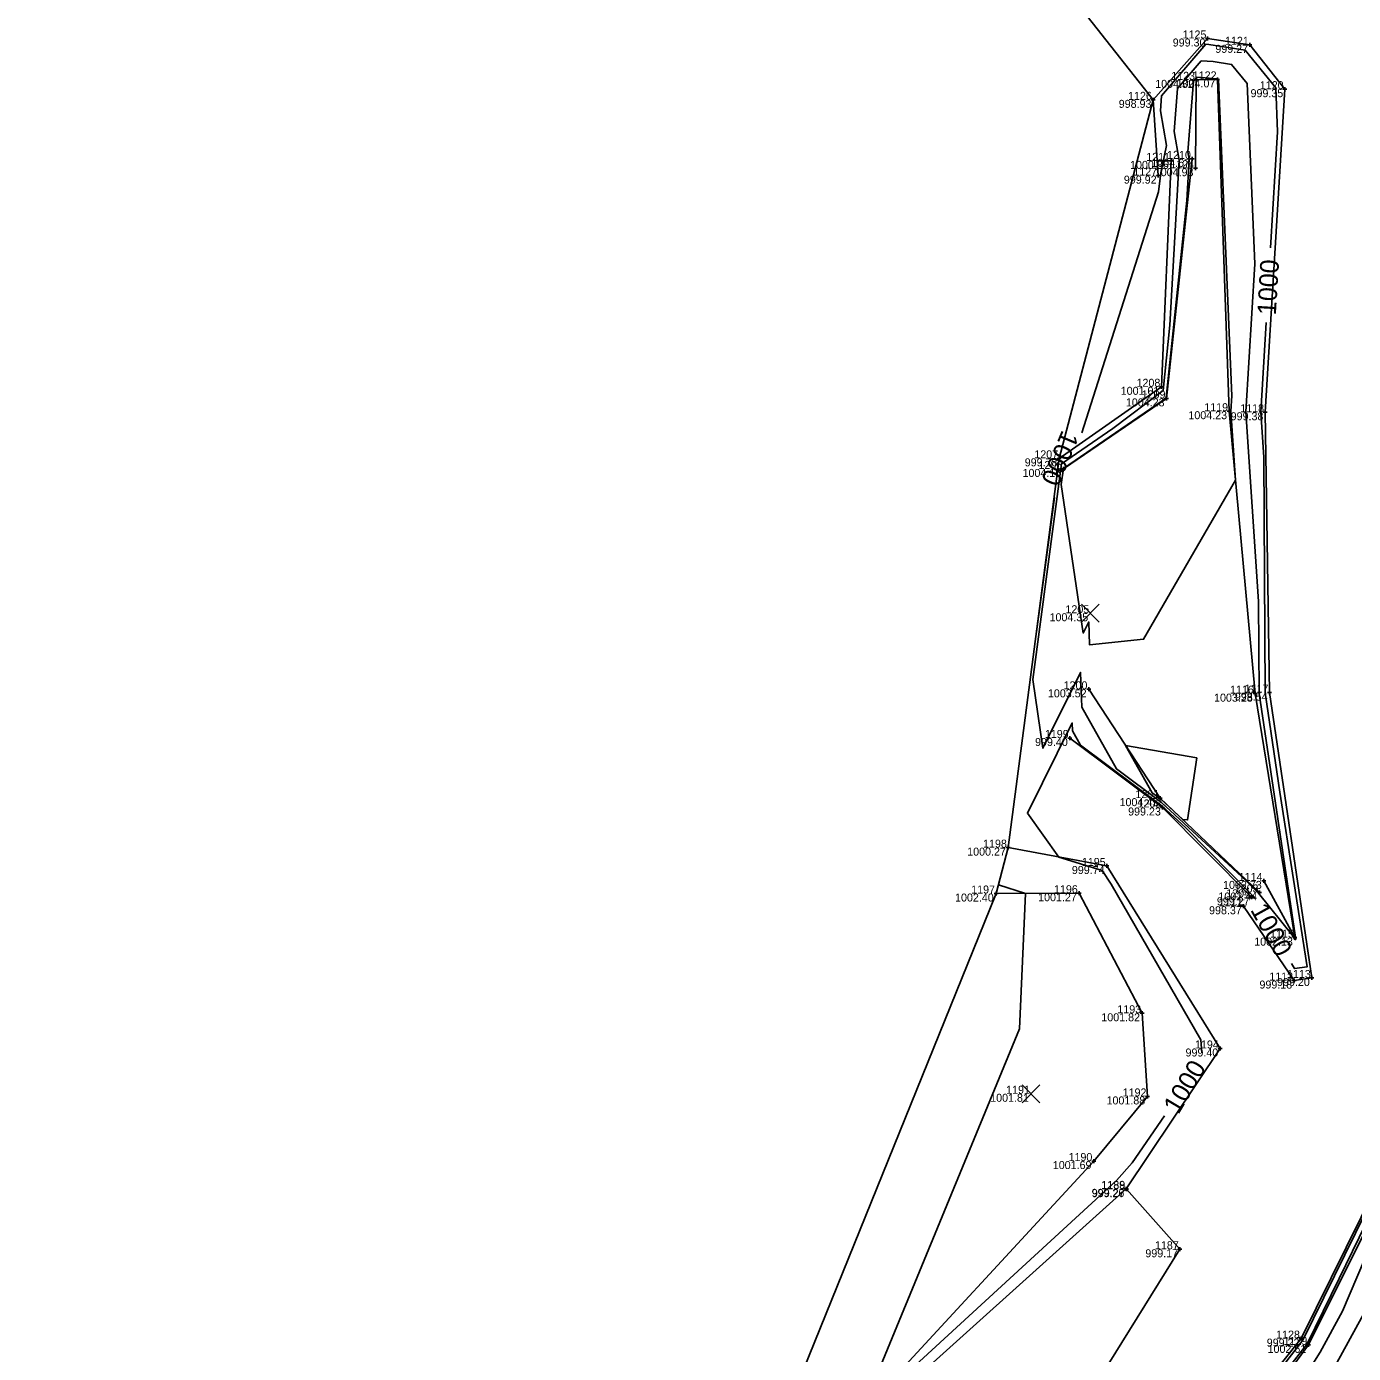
# Model space of a CAD drawing. Extents: x 2354693 to 2355622, y 637071 to 710080.
# Drawn here: x 2355058.5 to 2355257.5, y 708993.3 to 709192.3 of the extents above; entities that cross this region are included whole.
import ezdxf

# ---------------------------------------------------------------- set-up
doc = ezdxf.new("R2010")
doc.units = 0
for name, color, linetype in [('Default', 7, 'Continuous'), ('DT_X_Contour_Major', 7, 'Continuous'), ('DT_X_Contour_Minor', 7, 'Continuous'), ('HY_X_Water_Edge', 7, 'Continuous'), ('SV_X_Random_Point', 7, 'Continuous'), ('SV_X_Shot_Marker', 7, 'Continuous'), ('SV_X_Text_Elevation', 7, 'Continuous'), ('SV_X_Text_Name', 7, 'Continuous'), ('SV_X_Toe_of_Slope', 7, 'Continuous'), ('SV_X_Top_of_Bank', 7, 'Continuous')]:
    doc.layers.add(name, color=color, linetype=linetype)

msp = doc.modelspace()

# ---------------------------------------------------------------- linework, layer by layer
at = {"layer": 'Default'}
msp.add_lwpolyline([(2355192.85, 709575.71), (2355160.05, 709542.81), (2355116.76, 709509.42), (2355081.06, 709480.43), (2355058.46, 709461.11), (2355065.45, 709426.86), (2355078.86, 709361.48), (2355116.19, 709325.77), (2355146.4, 709319.01), (2355178.16, 709243.86), (2355227.43, 709181.3), (2355213.36, 709127.54), (2355205.69, 709069.16), (2355203.89, 709062.28), (2355168.12, 708973.83)], dxfattribs=at)
msp.add_lwpolyline([(2355192.85, 709575.71), (2355160.05, 709542.81), (2355116.76, 709509.42), (2355081.06, 709480.43), (2355058.46, 709461.11), (2355065.45, 709426.86), (2355078.86, 709361.48), (2355116.19, 709325.77), (2355146.4, 709319.01), (2355178.16, 709243.86), (2355227.43, 709181.3), (2355213.36, 709127.54), (2355205.69, 709069.16), (2355203.89, 709062.28), (2355168.12, 708973.83)], dxfattribs=at)
at = {"layer": 'DT_X_Contour_Major'}
for points in [[(2355245.05, 709159.09), (2355246.1, 709176.48), (2355245.82, 709183.1), (2355241.22, 709188.77), (2355235.8, 709189.61), (2355235.34, 709189.64), (2355228.71, 709181.9), (2355228.53, 709179.65), (2355229.45, 709174.47), (2355228.57, 709170.34), (2355228.25, 709167.53), (2355216.72, 709131.38)], [(2355245.05, 709159.09), (2355246.1, 709176.48), (2355245.82, 709183.1), (2355241.22, 709188.77), (2355235.8, 709189.61), (2355235.34, 709189.64), (2355228.71, 709181.9), (2355228.53, 709179.65), (2355229.45, 709174.47), (2355228.57, 709170.34), (2355228.25, 709167.53), (2355216.72, 709131.38)], [(2355248.17, 709051.77), (2355248.62, 709051.01), (2355250.54, 709051.27), (2355246.45, 709077.46), (2355244.23, 709092.36), (2355244.02, 709127.74), (2355243.57, 709134.47), (2355244.38, 709147.91)], [(2355248.17, 709051.77), (2355248.62, 709051.01), (2355250.54, 709051.27), (2355246.45, 709077.46), (2355244.23, 709092.36), (2355244.02, 709127.74), (2355243.57, 709134.47), (2355244.38, 709147.91)], [(2355212.63, 709121.69), (2355209.94, 709101.54)], [(2355212.63, 709121.69), (2355209.94, 709101.54)], [(2355234.76, 709038.38), (2355234.58, 709040.35), (2355221.12, 709063.67), (2355219.77, 709065.72), (2355213.31, 709067.74), (2355208.59, 709074.32), (2355215.31, 709087.87), (2355215.35, 709086.66), (2355216.54, 709084.53), (2355228.8, 709075.39), (2355232.33, 709072.12), (2355242.46, 709061.88), (2355242.77, 709061.49)], [(2355234.76, 709038.38), (2355234.58, 709040.35), (2355221.12, 709063.67), (2355219.77, 709065.72), (2355213.31, 709067.74), (2355208.59, 709074.32), (2355215.31, 709087.87), (2355215.35, 709086.66), (2355216.54, 709084.53), (2355228.8, 709075.39), (2355232.33, 709072.12), (2355242.46, 709061.88), (2355242.77, 709061.49)], [(2355274.9, 709071.46), (2355274.78, 709054.92), (2355274.64, 709045.69), (2355270.39, 709036.96), (2355249.89, 708995.32), (2355240.33, 708982.95), (2355238.86, 708980.97)], [(2355274.9, 709071.46), (2355274.78, 709054.92), (2355274.64, 709045.69), (2355270.39, 709036.96), (2355249.89, 708995.32), (2355240.33, 708982.95), (2355238.86, 708980.97)], [(2355167.69, 708952.51), (2355167.75, 708952.58), (2355178.96, 708965.48), (2355182.91, 708979.9), (2355184.16, 708983.1), (2355192.4, 708992.11), (2355221.92, 709019.26), (2355224.3, 709021.9), (2355229.14, 709028.96)], [(2355167.69, 708952.51), (2355167.75, 708952.58), (2355178.96, 708965.48), (2355182.91, 708979.9), (2355184.16, 708983.1), (2355192.4, 708992.11), (2355221.92, 709019.26), (2355224.3, 709021.9), (2355229.14, 709028.96)]]:
    msp.add_lwpolyline(points, dxfattribs=at)
at = {"layer": 'DT_X_Contour_Minor'}
for points in [[(2355248.44, 709055.83), (2355248.41, 709055.94), (2355243.23, 709062.33), (2355241.39, 709064.19), (2355228.67, 709075.92), (2355221.92, 709080.96), (2355216.73, 709090.21), (2355216.55, 709095.44), (2355210.91, 709084.07), (2355209.38, 709094.39), (2355213.69, 709126.73), (2355221.4, 709132.03), (2355228.94, 709137.73), (2355229.95, 709147.52), (2355231.34, 709172.27), (2355230.58, 709176.56), (2355231.1, 709183.01), (2355234.66, 709187.17), (2355236.44, 709187.03), (2355239.2, 709186.61), (2355241.54, 709183.73), (2355242.67, 709156.7), (2355241.34, 709134.53), (2355243.23, 709106.09), (2355243.32, 709092.29), (2355248.57, 709057.02), (2355248.82, 709055.39), (2355248.7, 709055.37), (2355248.44, 709055.83)], [(2355248.44, 709055.83), (2355248.41, 709055.94), (2355243.23, 709062.33), (2355241.39, 709064.19), (2355228.67, 709075.92), (2355221.92, 709080.96), (2355216.73, 709090.21), (2355216.55, 709095.44), (2355210.91, 709084.07), (2355209.38, 709094.39), (2355213.69, 709126.73), (2355221.4, 709132.03), (2355228.94, 709137.73), (2355229.95, 709147.52), (2355231.34, 709172.27), (2355230.58, 709176.56), (2355231.1, 709183.01), (2355234.66, 709187.17), (2355236.44, 709187.03), (2355239.2, 709186.61), (2355241.54, 709183.73), (2355242.67, 709156.7), (2355241.34, 709134.53), (2355243.23, 709106.09), (2355243.32, 709092.29), (2355248.57, 709057.02), (2355248.82, 709055.39), (2355248.7, 709055.37), (2355248.44, 709055.83)], [(2355233.48, 709184.12), (2355233.98, 709184.7), (2355237.09, 709184.46), (2355237.18, 709184.45), (2355237.25, 709184.35), (2355239.24, 709136.92), (2355239.1, 709134.6), (2355239.79, 709124.26), (2355226, 709100.42), (2355217.91, 709099.55), (2355217.79, 709103.01), (2355216.96, 709101.34), (2355213.66, 709123.61), (2355213.98, 709126), (2355228.64, 709136.07), (2355229.41, 709136.65), (2355232.47, 709166.23), (2355232.82, 709172.41), (2355232.63, 709173.48), (2355233.48, 709184.12)], [(2355233.48, 709184.12), (2355233.98, 709184.7), (2355237.09, 709184.46), (2355237.18, 709184.45), (2355237.25, 709184.35), (2355239.24, 709136.92), (2355239.1, 709134.6), (2355239.79, 709124.26), (2355226, 709100.42), (2355217.91, 709099.55), (2355217.79, 709103.01), (2355216.96, 709101.34), (2355213.66, 709123.61), (2355213.98, 709126), (2355228.64, 709136.07), (2355229.41, 709136.65), (2355232.47, 709166.23), (2355232.82, 709172.41), (2355232.63, 709173.48), (2355233.48, 709184.12)], [(2355228.54, 709076.46), (2355231.87, 709073.39), (2355232.6, 709073.31), (2355233.99, 709082.62), (2355223.31, 709084.48), (2355227.3, 709077.39), (2355228.54, 709076.46)], [(2355228.54, 709076.46), (2355231.87, 709073.39), (2355232.6, 709073.31), (2355233.99, 709082.62), (2355223.31, 709084.48), (2355227.3, 709077.39), (2355228.54, 709076.46)], [(2355106.5, 708911.01), (2355114.93, 708913.69), (2355139.33, 708933.32), (2355146.64, 708944.28), (2355156.1, 708946.64), (2355176.84, 708968.25), (2355181.12, 708978.77), (2355183.01, 708983.64), (2355184.37, 708985.13), (2355184.57, 708986.57), (2355207.42, 709041.98), (2355208.28, 709062.3), (2355204.23, 709063.58)], [(2355106.5, 708911.01), (2355114.93, 708913.69), (2355139.33, 708933.32), (2355146.64, 708944.28), (2355156.1, 708946.64), (2355176.84, 708968.25), (2355181.12, 708978.77), (2355183.01, 708983.64), (2355184.37, 708985.13), (2355184.57, 708986.57), (2355207.42, 709041.98), (2355208.28, 709062.3), (2355204.23, 709063.58)], [(2355275.38, 709045.66), (2355255.35, 709004.54), (2355250.54, 708994.76), (2355248.29, 708991.85)], [(2355275.38, 709045.66), (2355255.35, 709004.54), (2355250.54, 708994.76), (2355248.29, 708991.85)], [(2355270.65, 709034.41), (2355255.85, 708999.66), (2355252.48, 708993.49), (2355242.63, 708977.76)], [(2355270.65, 709034.41), (2355255.85, 708999.66), (2355252.48, 708993.49), (2355242.63, 708977.76)], [(2355263.24, 709006.97), (2355254.99, 708991.91)], [(2355263.24, 709006.97), (2355254.99, 708991.91)]]:
    msp.add_lwpolyline(points, dxfattribs=at)
at = {"layer": 'HY_X_Water_Edge'}
for points in [[(2355272.75, 709215.1), (2355272.74, 709215.09), (2355269.55, 709175.73), (2355269.77, 709147.81), (2355269.19, 709105.65), (2355274.67, 709084.44), (2355274.45, 709045.7), (2355249.64, 708995.53), (2355233.3, 708975.07), (2355214.48, 708950.61), (2355202.85, 708934.67), (2355185.21, 708913.18), (2355155.78, 708878.52), (2355144.35, 708868.9), (2355107.99, 708834.31)], [(2355241.01, 709060.37), (2355248.58, 709049.23), (2355251.23, 709049.61), (2355244.9, 709092.41), (2355244.26, 709134.45), (2355247.21, 709182.9), (2355241.95, 709189.55), (2355235.58, 709190.5), (2355227.43, 709181.3), (2355228.21, 709169.93)], [(2355093.48, 708843.59), (2355091.82, 708860.88), (2355101.34, 708874.79), (2355126.1, 708898.55), (2355156.73, 708937.57), (2355180.39, 708963.52), (2355184.45, 708982.97), (2355223.4, 709017.99), (2355237.5, 709039.04), (2355220.47, 709066.41), (2355205.69, 709069.16)]]:
    msp.add_lwpolyline(points, dxfattribs=at)
at = {"layer": 'SV_X_Random_Point'}
for p, q in [((2355216.68, 709102.98), (2355219.34, 709105.65)), ((2355216.68, 709105.65), (2355219.34, 709102.98)), ((2355207.79, 709030.91), (2355210.45, 709033.58)), ((2355207.79, 709033.58), (2355210.45, 709030.91))]:
    msp.add_line(p, q, dxfattribs=at)
at = {"layer": 'SV_X_Shot_Marker'}
for p, q in [((2355235.88, 709190.5), (2355235.28, 709190.5)), ((2355235.58, 709190.8), (2355235.58, 709190.2)), ((2355242.25, 709189.55), (2355241.65, 709189.55)), ((2355241.95, 709189.85), (2355241.95, 709189.25)), ((2355234.17, 709184.3), (2355233.57, 709184.3)), ((2355233.87, 709184.6), (2355233.87, 709184)), ((2355237.41, 709184.37), (2355236.81, 709184.37)), ((2355237.11, 709184.67), (2355237.11, 709184.07)), ((2355247.51, 709182.9), (2355246.91, 709182.9)), ((2355247.21, 709183.2), (2355247.21, 709182.6)), ((2355227.73, 709181.3), (2355227.13, 709181.3)), ((2355227.43, 709181.6), (2355227.43, 709181)), ((2355230.13, 709172.45), (2355230.13, 709171.85)), ((2355233.61, 709172.45), (2355233.01, 709172.45)), ((2355233.31, 709172.75), (2355233.31, 709172.15)), ((2355230.43, 709172.15), (2355229.83, 709172.15)), ((2355234.1, 709171.05), (2355233.5, 709171.05)), ((2355233.8, 709171.35), (2355233.8, 709170.75)), ((2355228.51, 709169.93), (2355227.92, 709169.93)), ((2355228.21, 709170.23), (2355228.21, 709169.63)), ((2355228.71, 709138.57), (2355228.71, 709137.97)), ((2355229.01, 709138.27), (2355228.41, 709138.27)), ((2355229.76, 709136.53), (2355229.16, 709136.53)), ((2355229.46, 709136.83), (2355229.46, 709136.23)), ((2355239.14, 709134.61), (2355238.54, 709134.61)), ((2355238.84, 709134.91), (2355238.84, 709134.31)), ((2355244.56, 709134.45), (2355243.96, 709134.45)), ((2355244.26, 709134.75), (2355244.26, 709134.15)), ((2355213.66, 709127.54), (2355213.06, 709127.54)), ((2355213.36, 709127.84), (2355213.36, 709127.24)), ((2355214.3, 709125.95), (2355213.7, 709125.95)), ((2355214, 709126.25), (2355214, 709125.65)), ((2355218.08, 709092.9), (2355217.48, 709092.9)), ((2355217.78, 709093.2), (2355217.78, 709092.6)), ((2355244.9, 709092.71), (2355244.9, 709092.11)), ((2355243.03, 709092.25), (2355242.43, 709092.25)), ((2355242.73, 709092.55), (2355242.73, 709091.95)), ((2355245.2, 709092.41), (2355244.6, 709092.41)), ((2355215.23, 709085.6), (2355214.63, 709085.6)), ((2355214.93, 709085.9), (2355214.93, 709085.3)), ((2355228.51, 709076.88), (2355228.51, 709076.28)), ((2355228.81, 709076.58), (2355228.21, 709076.58)), ((2355229.14, 709075.18), (2355228.54, 709075.18)), ((2355228.84, 709075.48), (2355228.84, 709074.88)), ((2355205.98, 709069.16), (2355205.39, 709069.16)), ((2355205.69, 709069.46), (2355205.69, 709068.86)), ((2355220.77, 709066.41), (2355220.17, 709066.41)), ((2355220.47, 709066.71), (2355220.47, 709066.11)), ((2355244.34, 709064.17), (2355243.74, 709064.17)), ((2355244.04, 709064.47), (2355244.04, 709063.87)), ((2355204.19, 709062.28), (2355203.59, 709062.28)), ((2355203.89, 709062.58), (2355203.89, 709061.98)), ((2355216.62, 709062.32), (2355216.02, 709062.32)), ((2355216.32, 709062.62), (2355216.32, 709062.02)), ((2355242.48, 709061.71), (2355241.88, 709061.71)), ((2355242.18, 709062.01), (2355242.18, 709061.41)), ((2355243.7, 709062.44), (2355243.1, 709062.44)), ((2355243.4, 709062.74), (2355243.4, 709062.14)), ((2355241.31, 709060.37), (2355240.71, 709060.37)), ((2355241.01, 709060.67), (2355241.01, 709060.07)), ((2355249.01, 709055.66), (2355248.41, 709055.66)), ((2355248.71, 709055.96), (2355248.71, 709055.36)), ((2355248.88, 709049.23), (2355248.28, 709049.23)), ((2355248.58, 709049.53), (2355248.58, 709048.93)), ((2355251.53, 709049.61), (2355250.93, 709049.61)), ((2355251.23, 709049.91), (2355251.23, 709049.31)), ((2355226.09, 709044.32), (2355225.49, 709044.32)), ((2355225.79, 709044.62), (2355225.79, 709044.02)), ((2355237.8, 709039.04), (2355237.2, 709039.04)), ((2355237.5, 709039.34), (2355237.5, 709038.74)), ((2355226.9, 709031.85), (2355226.3, 709031.85)), ((2355226.6, 709032.15), (2355226.6, 709031.55)), ((2355218.82, 709022.16), (2355218.22, 709022.16)), ((2355218.52, 709022.46), (2355218.52, 709021.86)), ((2355223.7, 709017.99), (2355223.1, 709017.99)), ((2355223.73, 709017.94), (2355223.13, 709017.94)), ((2355223.4, 709018.29), (2355223.4, 709017.69)), ((2355223.43, 709018.24), (2355223.43, 709017.64)), ((2355231.45, 709009.23), (2355231.45, 709008.63)), ((2355231.75, 709008.93), (2355231.15, 709008.93)), ((2355249.94, 708995.53), (2355249.34, 708995.53)), ((2355249.64, 708995.83), (2355249.64, 708995.23)), ((2355251.04, 708994.59), (2355250.44, 708994.59)), ((2355250.74, 708994.89), (2355250.74, 708994.29))]:
    msp.add_line(p, q, dxfattribs=at)
at = {"layer": 'SV_X_Toe_of_Slope'}
for points in [[(2355342.79, 709267.27), (2355319.66, 709264.93), (2355304.72, 709256.21), (2355286.48, 709242.45), (2355272.74, 709215.09), (2355269.55, 709175.73), (2355269.77, 709147.81), (2355269.19, 709105.65), (2355274.67, 709084.44), (2355274.45, 709045.7), (2355249.64, 708995.53), (2355233.3, 708975.07), (2355214.48, 708950.61), (2355202.85, 708934.67), (2355185.21, 708913.18), (2355155.78, 708878.52), (2355144.35, 708868.9), (2355107.99, 708834.31)], [(2355241.01, 709060.37), (2355248.58, 709049.23), (2355251.23, 709049.61), (2355244.9, 709092.41), (2355244.26, 709134.45), (2355247.21, 709182.9), (2355241.95, 709189.55), (2355235.58, 709190.5), (2355227.43, 709181.3), (2355228.21, 709169.93)], [(2355213.36, 709127.54), (2355228.71, 709138.27), (2355230.13, 709172.15)], [(2355214.93, 709085.6), (2355228.84, 709075.18), (2355242.18, 709061.71)], [(2355093.48, 708843.59), (2355091.82, 708860.88), (2355101.34, 708874.79), (2355126.1, 708898.55), (2355156.73, 708937.57), (2355180.39, 708963.52), (2355184.45, 708982.97), (2355223.4, 709017.99), (2355237.5, 709039.04), (2355220.47, 709066.41), (2355205.69, 709069.16)], [(2355186.24, 708974.37), (2355217.51, 708986.49), (2355231.45, 709008.93), (2355223.43, 709017.94)]]:
    msp.add_lwpolyline(points, dxfattribs=at)
at = {"layer": 'SV_X_Top_of_Bank'}
for points in [[(2355273.36, 709199.07), (2355271.07, 709175.55), (2355271.92, 709154.64), (2355272.23, 709141.56), (2355270.63, 709105.68), (2355275.83, 709084.35), (2355276.25, 709045.62), (2355250.74, 708994.59), (2355235.32, 708973.62), (2355222.78, 708949.56), (2355205.08, 708933.16), (2355186.58, 708911.43), (2355156.5, 708876.84), (2355146.53, 708867.02), (2355127.53, 708842.2), (2355110.99, 708831.54)], [(2355244.04, 709064.17), (2355248.71, 709055.66), (2355242.73, 709092.25), (2355238.84, 709134.61), (2355237.11, 709184.37), (2355233.87, 709184.3), (2355233.8, 709171.05)], [(2355214, 709125.95), (2355229.46, 709136.53), (2355233.31, 709172.45)], [(2355217.78, 709092.9), (2355228.51, 709076.58), (2355243.4, 709062.44)], [(2355092.11, 708843.77), (2355088.4, 708864.8), (2355120.83, 708903.46), (2355153.14, 708939.92), (2355177.02, 708968.14), (2355183, 708983.64), (2355218.52, 709022.16), (2355226.6, 709031.85), (2355225.79, 709044.32), (2355216.32, 709062.32), (2355203.89, 709062.28)]]:
    msp.add_lwpolyline(points, dxfattribs=at)

# ---------------------------------------------------------------- texts
at = {"layer": 'DT_X_Contour_Major'}
for rotation, p in [(86.5596, (2355245.84, 709148.96)), (86.5596, (2355245.84, 709148.96)), (247.1135, (2355213.81, 709131.9)), (247.1135, (2355213.81, 709131.9)), (299.0407, (2355241.96, 709059.84)), (299.0407, (2355241.96, 709059.84)), (59.1928, (2355231.22, 709029.03)), (59.1928, (2355231.22, 709029.03))]:
    msp.add_text('1000', height=2.8, rotation=rotation, dxfattribs=at).set_placement(p)
at = {"layer": 'SV_X_Text_Elevation'}
for s, p in [('999.30', (2355230.38, 709189.3)), ('999.27', (2355236.77, 709188.35)), ('1004.32', (2355227.75, 709183.1)), ('1004.07', (2355230.97, 709183.17)), ('999.35', (2355242.05, 709181.7)), ('998.93', (2355222.28, 709180.1)), ('1004.67', (2355227.17, 709171.25)), ('1000.36', (2355223.98, 709170.95)), ('1004.93', (2355227.69, 709169.85)), ('999.92', (2355223.05, 709168.73)), ('1001.01', (2355222.58, 709137.07)), ('1004.23', (2355223.35, 709135.33)), ('1004.23', (2355232.73, 709133.41)), ('999.38', (2355239.07, 709133.25)), ('999.78', (2355208.18, 709126.34)), ('1004.16', (2355207.85, 709124.75)), ('1004.35', (2355211.9, 709103.11)), ('1003.52', (2355211.66, 709091.7)), ('1003.28', (2355236.58, 709091.05)), ('998.54', (2355239.69, 709091.21)), ('999.40', (2355209.73, 709084.4)), ('1004.45', (2355222.4, 709075.38)), ('999.23', (2355223.69, 709073.98)), ('1000.27', (2355199.55, 709067.96)), ('999.74', (2355215.25, 709065.21)), ('1002.73', (2355237.93, 709062.97)), ('1002.40', (2355197.73, 709061.08)), ('1001.27', (2355210.19, 709061.12)), ('999.27', (2355237, 709060.51)), ('1002.44', (2355237.23, 709061.24)), ('998.37', (2355235.83, 709059.17)), ('1002.13', (2355242.6, 709054.46)), ('999.18', (2355243.39, 709048.03)), ('999.20', (2355246.03, 709048.41)), ('1001.82', (2355219.67, 709043.12)), ('999.40', (2355232.3, 709037.84)), ('1001.81', (2355203, 709031.05)), ('1001.88', (2355220.45, 709030.65)), ('1001.69', (2355212.39, 709020.96)), ('999.26', (2355218.21, 709016.79)), ('999.27', (2355218.25, 709016.74)), ('999.17', (2355226.27, 709007.73)), ('999.22', (2355244.48, 708994.33)), ('1002.61', (2355244.61, 708993.39))]:
    msp.add_text(s, height=1.2, dxfattribs=at).set_placement(p)
at = {"layer": 'SV_X_Text_Name'}
for s, p in [('1125', (2355231.86, 709190.5)), ('1121', (2355238.22, 709189.55)), ('1123', (2355230.15, 709184.3)), ('1122', (2355233.38, 709184.37)), ('1126', (2355223.68, 709181.3)), ('1120', (2355243.44, 709182.9)), ('1211', (2355226.41, 709172.15)), ('1210', (2355229.54, 709172.45)), ('1124', (2355230.02, 709171.05)), ('1127', (2355224.47, 709169.93)), ('1208', (2355224.95, 709138.27)), ('1209', (2355225.72, 709136.53)), ('1119', (2355235.11, 709134.61)), ('1118', (2355240.51, 709134.45)), ('1207', (2355209.62, 709127.54)), ('1206', (2355210.24, 709125.95)), ('1205', (2355214.29, 709104.31)), ('1200', (2355214.01, 709092.9)), ('1116', (2355238.97, 709092.25)), ('1117', (2355241.16, 709092.41)), ('1199', (2355211.2, 709085.6)), ('1201', (2355224.78, 709076.58)), ('1202', (2355225.12, 709075.18)), ('1198', (2355201.93, 709069.16)), ('1195', (2355216.75, 709066.41)), ('1114', (2355240.27, 709064.17)), ('1197', (2355200.15, 709062.28)), ('1196', (2355212.57, 709062.32)), ('1204', (2355238.4, 709061.71)), ('1203', (2355239.68, 709062.44)), ('1111', (2355237.28, 709060.37)), ('1115', (2355244.99, 709055.66)), ('1112', (2355244.86, 709049.23)), ('1113', (2355247.52, 709049.61)), ('1193', (2355222.07, 709044.32)), ('1194', (2355233.72, 709039.04)), ('1191', (2355205.39, 709032.25)), ('1192', (2355222.87, 709031.85)), ('1190', (2355214.75, 709022.16)), ('1189', (2355219.67, 709017.99)), ('1188', (2355219.68, 709017.94)), ('1187', (2355227.71, 709008.93)), ('1128', (2355245.89, 708995.53)), ('1129', (2355247, 708994.59))]:
    msp.add_text(s, height=1.2, dxfattribs=at).set_placement(p)

doc.saveas('drawing.dxf')
